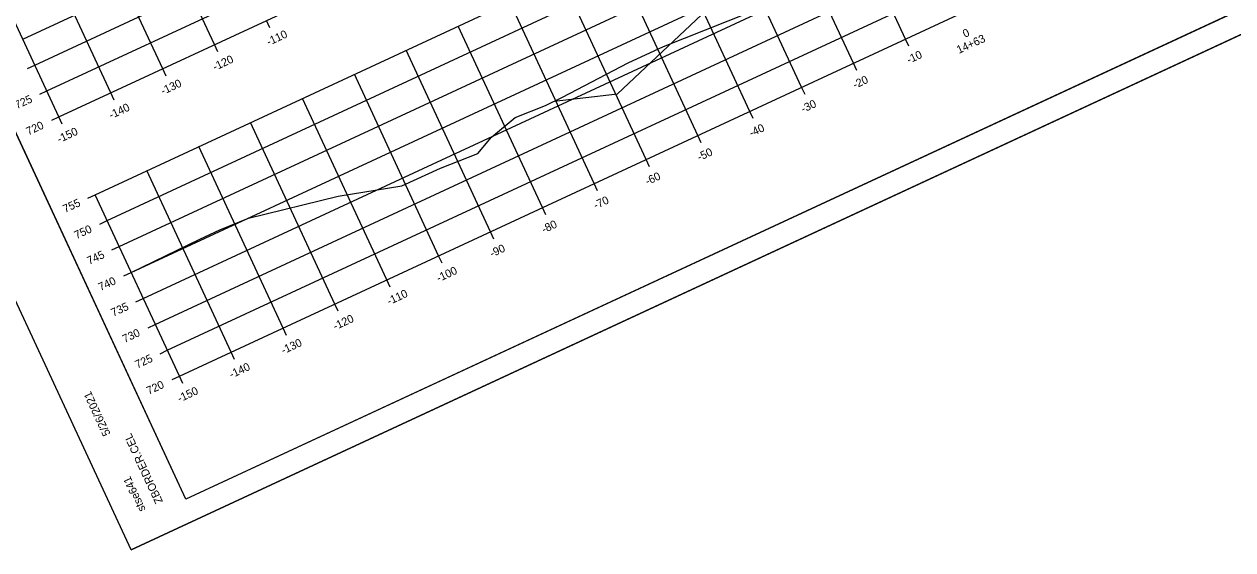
# Model space of a CAD drawing. Extents: x 1354696 to 1366163, y 660729 to 670380.
# Drawn here: x 1358843.9 to 1359055.3, y 665712.2 to 665804.1 of the extents above; entities that cross this region are included whole.
import ezdxf

# ---------------------------------------------------------------- set-up
doc = ezdxf.new("R2010")
doc.units = 0
for name, color, linetype in [('R_Axis', 7, 'Continuous'), ('R_Axis Annot', 7, 'Continuous'), ('R_Border', 7, 'Continuous'), ('R_Exist Surface', 7, 'Continuous'), ('R_Fin Surface', 7, 'Continuous'), ('R_Grid', 7, 'Continuous'), ('R_No Plot', 7, 'Continuous')]:
    doc.layers.add(name, color=color, linetype=linetype)

msp = doc.modelspace()

# ---------------------------------------------------------------- linework, layer by layer
at = {"layer": 'R_Axis'}
for p, q in [((1358850.01, 665787.89), (1359122.12, 665914.22)), ((1358871.07, 665742.54), (1359143.17, 665868.87)), ((1358850.01, 665787.89), (1358835.27, 665819.64)), ((1358886.88, 665803.47), (1358886.29, 665804.74)), ((1358998.64, 665800.23), (1358998.05, 665801.5)), ((1358877.81, 665799.26), (1358877.22, 665800.53)), ((1358844.53, 665796.37), (1358845.8, 665796.96)), ((1358989.57, 665796.02), (1358988.98, 665797.29)), ((1358868.74, 665795.04), (1358868.15, 665796.31)), ((1358846.64, 665791.84), (1358847.91, 665792.43)), ((1358980.5, 665791.8), (1358979.91, 665793.07)), ((1358859.67, 665790.83), (1358859.08, 665792.1)), ((1358971.43, 665787.59), (1358970.84, 665788.86)), ((1358848.74, 665787.3), (1358850.01, 665787.89)), ((1358850.6, 665786.62), (1358850.01, 665787.89)), ((1358962.36, 665783.38), (1358961.77, 665784.65)), ((1358953.29, 665779.17), (1358952.7, 665780.44)), ((1358944.22, 665774.96), (1358943.63, 665776.23)), ((1358855.06, 665773.7), (1358856.33, 665774.29)), ((1358871.07, 665742.54), (1358856.33, 665774.29)), ((1358935.15, 665770.75), (1358934.56, 665772.02)), ((1358857.17, 665769.16), (1358858.44, 665769.75)), ((1358926.08, 665766.54), (1358925.49, 665767.81)), ((1358859.27, 665764.63), (1358860.54, 665765.22)), ((1358917.01, 665762.33), (1358916.42, 665763.6)), ((1358861.38, 665760.09), (1358862.65, 665760.68)), ((1358907.94, 665758.12), (1358907.35, 665759.39)), ((1358863.48, 665755.56), (1358864.75, 665756.15)), ((1358898.87, 665753.91), (1358898.28, 665755.17)), ((1358865.59, 665751.02), (1358866.86, 665751.61)), ((1358889.8, 665749.69), (1358889.21, 665750.96)), ((1358867.69, 665746.49), (1358868.96, 665747.08)), ((1358880.73, 665745.48), (1358880.14, 665746.75)), ((1358869.8, 665741.95), (1358871.07, 665742.54)), ((1358871.66, 665741.27), (1358871.07, 665742.54))]:
    msp.add_line(p, q, dxfattribs=at)
at = {"layer": 'R_Border'}
for p, q in [((1358872.23, 665721.03), (1358785.71, 665907.39)), ((1359159.01, 665854.18), (1358872.23, 665721.03)), ((1358872.23, 665721.03), (1358872.23, 665721.03))]:
    msp.add_line(p, q, dxfattribs=at)
at = {"layer": 'R_Exist Surface'}
msp.add_lwpolyline([(1358862.65, 665760.67), (1358874.64, 665766.5), (1358878.14, 665768.15), (1358883.16, 665770.19), (1358898.85, 665774.04), (1358909.97, 665775.83), (1358916.73, 665778.91), (1358923.29, 665781.48), (1358925.64, 665784.33), (1358929.8, 665787.81), (1358935.12, 665789.89), (1358938.08, 665791.35), (1358949.55, 665797.37), (1358955.77, 665800.19), (1358974.39, 665807.61)], dxfattribs=at)
at = {"layer": 'R_Fin Surface'}
msp.add_lwpolyline([(1358936.65, 665790.65), (1358947.7, 665791.9), (1358971.24, 665814.12), (1358974.3, 665816.16), (1358981.35, 665820.85), (1358986.74, 665823.49), (1358996.62, 665828.32), (1359006.69, 665832.75), (1359012.24, 665835.06), (1359019.88, 665837.33), (1359023.86, 665838.51), (1359059.06, 665842.5), (1359075.59, 665858.1)], dxfattribs=at)
at = {"layer": 'R_Grid'}
for p, q in [((1358843.7, 665801.5), (1359115.8, 665927.83)), ((1358845.8, 665796.96), (1359117.91, 665923.29)), ((1358847.91, 665792.43), (1359120.01, 665918.76)), ((1358850.01, 665787.89), (1359122.12, 665914.22)), ((1358856.33, 665774.29), (1359128.43, 665900.62)), ((1358858.44, 665769.75), (1359130.54, 665896.08)), ((1358860.54, 665765.22), (1359132.65, 665891.55)), ((1358862.65, 665760.68), (1359134.75, 665887.01)), ((1358864.75, 665756.15), (1359136.86, 665882.48)), ((1358866.86, 665751.61), (1359138.96, 665877.94)), ((1358868.96, 665747.08), (1359141.07, 665873.41)), ((1358871.07, 665742.54), (1359143.17, 665868.87)), ((1358998.05, 665801.5), (1358983.31, 665833.24)), ((1358877.22, 665800.53), (1358862.49, 665832.27)), ((1358988.98, 665797.29), (1358974.24, 665829.03)), ((1358868.15, 665796.31), (1358853.42, 665828.06)), ((1358979.91, 665793.07), (1358965.17, 665824.82)), ((1358859.08, 665792.1), (1358844.35, 665823.85)), ((1358970.84, 665788.86), (1358956.1, 665820.61)), ((1358850.01, 665787.89), (1358835.27, 665819.64)), ((1358961.77, 665784.65), (1358947.03, 665816.4)), ((1358952.7, 665780.44), (1358937.96, 665812.19)), ((1358943.63, 665776.23), (1358928.89, 665807.98)), ((1358934.56, 665772.02), (1358919.82, 665803.76)), ((1358925.49, 665767.81), (1358910.75, 665799.55)), ((1358916.42, 665763.6), (1358901.68, 665795.34)), ((1358907.35, 665759.39), (1358892.61, 665791.13)), ((1358898.28, 665755.17), (1358883.54, 665786.92)), ((1358889.21, 665750.96), (1358874.47, 665782.71)), ((1358880.14, 665746.75), (1358865.4, 665778.5)), ((1358871.07, 665742.54), (1358856.33, 665774.29))]:
    msp.add_line(p, q, dxfattribs=at)
at = {"layer": 'R_No Plot'}
msp.add_line((1358862.66, 665712.2), (1359165, 665852.57), dxfattribs=at)
for points in [[(1358772.82, 665905.7), (1359075.16, 666046.07), (1359165, 665852.57), (1358862.66, 665712.2)], [(1358997.88, 666005.89), (1359015.68, 666014.15), (1359019.84, 666005.19), (1359034.45, 666011.98), (1359055.5, 666021.75), (1359067.46, 665996.26), (1359088.51, 666006.03), (1359159.01, 665854.18), (1358872.23, 665721.03), (1358785.71, 665907.39)]]:
    msp.add_lwpolyline(points, close=True, dxfattribs=at)

# ---------------------------------------------------------------- texts
at = {"layer": 'R_Axis Annot'}
for s, p in [('-110', (1358886.71, 665800.3)), ('0', (1359008.47, 665801.7)), ('14+63', (1359007.41, 665798.9)), ('-120', (1358877.28, 665795.92)), ('-10', (1358998.67, 665797.16)), ('-130', (1358868.21, 665791.71)), ('-20', (1358989.24, 665792.78)), ('725', (1358842.66, 665789.22)), ('-140', (1358859.14, 665787.5)), ('-30', (1358980.17, 665788.57)), ('720', (1358844.66, 665784.63)), ('-150', (1358850.07, 665783.29)), ('-40', (1358971.1, 665784.35)), ('-50', (1358962.03, 665780.14)), ('-60', (1358952.93, 665775.92)), ('755', (1358851.09, 665771.08)), ('-70', (1358943.89, 665771.72)), ('-80', (1358934.82, 665767.51)), ('750', (1358853.08, 665766.49)), ('-90', (1358925.75, 665763.3)), ('745', (1358855.3, 665762.01)), ('-100', (1358916.42, 665758.97)), ('740', (1358857.29, 665757.42)), ('-110', (1358907.76, 665754.95)), ('735', (1358859.51, 665752.94)), ('-120', (1358898.33, 665750.57)), ('730', (1358861.5, 665748.35)), ('-130', (1358889.26, 665746.36)), ('725', (1358863.72, 665743.87)), ('-140', (1358880.19, 665742.15)), ('720', (1358865.71, 665739.28)), ('-150', (1358871.12, 665737.94))]:
    msp.add_text(s, height=1.4, rotation=24.9042, dxfattribs=at).set_placement(p)
at = {"layer": 'R_Border'}
for s, p in [('5/26/2021', (1358859.06, 665732.47)), ('ZBORDER.CEL', (1358868.22, 665720.63)), ('stse641', (1358865.21, 665719.23))]:
    msp.add_text(s, height=1.4, rotation=114.9042, dxfattribs=at).set_placement(p)

doc.saveas('drawing.dxf')
